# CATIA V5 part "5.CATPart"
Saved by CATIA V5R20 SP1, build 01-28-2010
Part number: 5
Publications: "E", "G", "Droite.1", "Droite.2", "Droite.3", "Droite.4", "Droite.5", "Droite.6", "A", "E1", "G1", "Droite.7", "Droite.8", "Droite.9", "Droite.10", "Droite.11", "Droite.12", "Plan.1"
Bounding box of the stored display mesh (mm): x 0 to 0, y 0 to 46.109, z 0 to 24.962
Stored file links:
  C:\Users\Geoffray\Documents\Ifma\IAO\Exercice IAO\Catia\5.CATPart
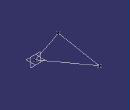
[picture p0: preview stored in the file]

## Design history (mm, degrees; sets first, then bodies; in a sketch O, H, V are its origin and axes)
Parameters
  AE = 30 mm
  AG = 50 mm
  EG = 30 mm
Body1 (main body)
  Point1 "A": (0, 0, 0)
  Point2 to Point5 "A": stored without definition
  Sketch1 on yz-plane, origin (0, 0, 0), H (0, 1, 0), V (0, 0, 1)
    circle A1 centre (0, 0) radius 30
    reference projected point E1 (0, 0) from Point2
    distance E1 A1 = 30 {= AE}
  Point6 "E": type OnCurve, Support Sketch1, RefPoint {extremum Reference Sketch1, Direction (1, 2, 3)}, Length 0
  Point7 "A": stored without definition
  Sketch2 on yz-plane, origin (0, 0, 0), H (0, 1, 0), V (0, 0, 1)
    circle A1 centre (0, 0) radius 50
    reference projected point E1 (0, 0) from Point7
    distance E1 A1 = 50 {= AG}
  Sketch3 on yz-plane, origin (0, 0, 0), H (0, 1, 0), V (0, 0, 1)
    circle A1 centre (16.641, 24.9615) radius 30
    point P1 (16.641, 24.9615)
    reference projected point E1 (16.641, 24.9615) from Point6
    reference projected point E2 (16.641, 24.9615) from Point6
    reference projected circle E3 centre (0, 0) radius 50 from Sketch2.A1
    point P2 (0.1159, 49.9999)
    point P3 (46.1092, 19.3377)
    distance E2 A1 = 30 {= EG}
    coincidence: P1 E1, A1 P2, E3 P2, A1 P3, E3 P3
  Point8 "G": (0, 0, 0), relative to Sketch3.P3
  Line1: type PtDir, RefPoint Point1, Direction yz-plane, Start -50, End 50
  Line2: type PtDir, RefPoint Point6, Direction yz-plane, Start -50, End 50
  Line3: type PtDir, RefPoint Point8, Direction yz-plane, Start -50, End 50
  Line4: type PtPt, FirstPoint Point1, SecondPoint Point6
  Line5: type PtPt, FirstPoint Point6, SecondPoint Sketch3.P3
  Line6: type PtPt, FirstPoint Point1, SecondPoint Sketch3.P3
  Plane1: type Offset, RefPlane yz-plane, Offset 0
